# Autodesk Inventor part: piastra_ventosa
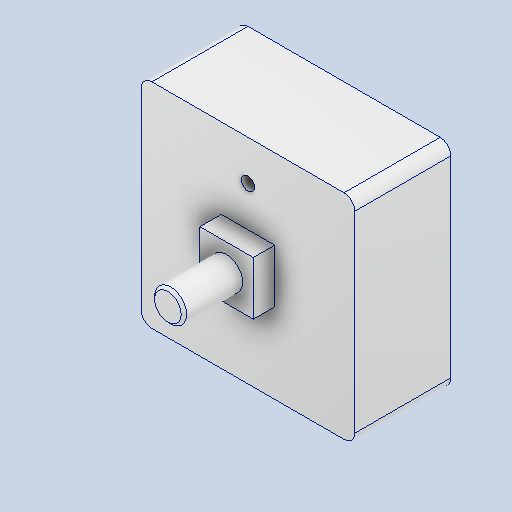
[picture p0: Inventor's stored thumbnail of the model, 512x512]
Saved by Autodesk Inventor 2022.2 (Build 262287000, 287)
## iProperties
Created: 2024-10
Part Number: piastra_ventosa
Material: Alluminio 6061
Document SubType Name: Modeling
Designer: 18907419
Density: 2.7 g/cm^3
Appearance: Default
Author: 18907419
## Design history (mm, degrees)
feature "Solido1"
node "Solido2"
